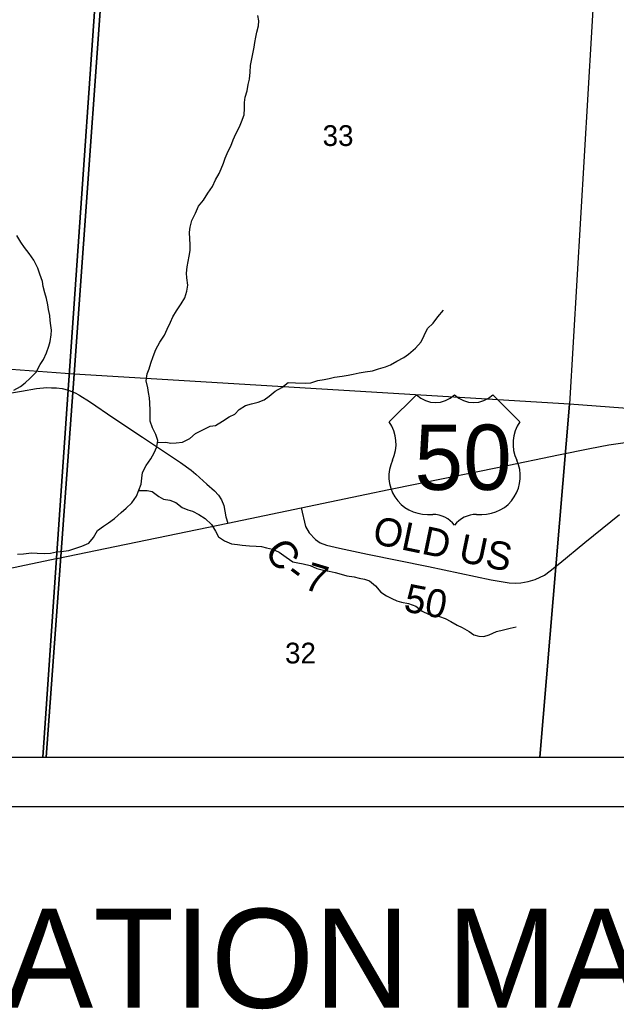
# Model space of a CAD drawing. Extents: x 0 to 34, y 0 to 22.
# Drawn here: x 5.007 to 6.21, y 13.591 to 15.589 of the extents above; entities that cross this region are included whole.
import ezdxf

# ---------------------------------------------------------------- set-up
doc = ezdxf.new("R2010")
doc.units = 0
for name, color, linetype in [('Default', 7, 'Continuous'), ('GM_X_County_Road', 7, 'Continuous'), ('GM_X_County_Road_Text', 7, 'Continuous'), ('GM_X_Minor_River', 7, 'Continuous'), ('GM_X_Section', 7, 'Continuous'), ('GM_X_Section_Text', 7, 'Continuous'), ('GM_X_US_Location', 7, 'Continuous'), ('GM_X_US_Route', 7, 'Continuous'), ('GM_X_US_Shield', 7, 'Continuous'), ('SC_Scratch1', 7, 'Continuous'), ('SH_Data', 7, 'Continuous'), ('SH_Text', 7, 'Continuous')]:
    doc.layers.add(name, color=color, linetype=linetype)

msp = doc.modelspace()

# ---------------------------------------------------------------- linework, layer by layer
at = {"layer": 'Default'}
for points in [[(4.0548, 14.1), (5.0601, 14.1), (5.117, 14.8733), (4.1172, 14.9476)], [(5.0601, 14.1), (6.0561, 14.1), (6.1161, 14.8127), (5.117, 14.8733)], [(6.0561, 14.1), (7.0384, 14.1), (7.0398, 14.1229), (7.0661, 14.5598), (7.0761, 14.7365), (6.6458, 14.7734), (6.1161, 14.8127)]]:
    msp.add_lwpolyline(points, close=True, dxfattribs=at)
at = {"layer": 'GM_X_County_Road'}
msp.add_line((5.4268, 14.5725), (5.5748, 14.6035), dxfattribs=at)
for points in [[(4.9443, 14.8282), (5.0106, 14.8388), (5.041, 14.8443), (5.0614, 14.8464), (5.0708, 14.8461), (5.0812, 14.8457), (5.0925, 14.8441), (5.1051, 14.8409), (5.1069, 14.8404), (5.1187, 14.836), (5.1262, 14.8313)], [(5.1262, 14.8313), (5.1279, 14.8302), (5.1477, 14.818), (5.1969, 14.7847), (5.2544, 14.7462), (5.3013, 14.715), (5.3311, 14.6952), (5.3526, 14.6793), (5.3621, 14.6711), (5.3842, 14.6511), (5.4001, 14.6378), (5.4082, 14.6293), (5.4141, 14.6199), (5.4185, 14.6084), (5.423, 14.5851), (5.4268, 14.5725)], [(5.5748, 14.6035), (5.5834, 14.566), (5.591, 14.5532), (5.6035, 14.5393), (5.6131, 14.5328), (5.6259, 14.5279), (5.6523, 14.5219), (5.7088, 14.5097), (5.8318, 14.4848), (5.9583, 14.4581), (5.9942, 14.4522), (6.0077, 14.4516), (6.0179, 14.4522), (6.0326, 14.4546), (6.0469, 14.4589), (6.0656, 14.4673), (6.0775, 14.4764), (6.0964, 14.4919), (6.147, 14.5332), (6.2168, 14.5903)]]:
    msp.add_lwpolyline(points, dxfattribs=at)
at = {"layer": 'GM_X_Minor_River'}
for points in [[(5.4703, 15.4694), (5.4717, 15.4833), (5.4728, 15.4969), (5.4743, 15.5068), (5.4773, 15.5205), (5.4799, 15.5337), (5.4814, 15.5432), (5.4836, 15.5542), (5.4851, 15.5637), (5.4885, 15.577), (5.4896, 15.5872), (5.4877, 15.5975)], [(5.0024, 14.5096), (5.0145, 14.5108), (5.0308, 14.5126), (5.0421, 14.5122), (5.0572, 14.5111), (5.069, 14.5122), (5.0814, 14.5148), (5.0951, 14.5159), (5.1057, 14.5174), (5.1321, 14.5257), (5.1461, 14.5322), (5.156, 14.5435), (5.1636, 14.5575), (5.1761, 14.5662), (5.1863, 14.5734), (5.198, 14.5821), (5.2117, 14.5938), (5.2215, 14.6025), (5.2333, 14.6135), (5.2427, 14.6271), (5.2473, 14.6389), (5.2519, 14.6514), (5.253, 14.6635), (5.2549, 14.6749), (5.2618, 14.6889), (5.2716, 14.7025), (5.2784, 14.7146), (5.2838, 14.7268), (5.2857, 14.7396), (5.2819, 14.7518), (5.2747, 14.7647), (5.2698, 14.7783), (5.2699, 14.7904), (5.2703, 14.8003), (5.2695, 14.8158), (5.2688, 14.8257), (5.2669, 14.8363), (5.2654, 14.8458), (5.262, 14.8602), (5.264, 14.8738), (5.2678, 14.8844), (5.2715, 14.8954), (5.2761, 14.909), (5.2818, 14.9231), (5.2894, 14.9378), (5.2989, 14.9522), (5.3046, 14.9643), (5.311, 14.9787), (5.316, 14.9889), (5.3235, 15.0011), (5.333, 15.0151), (5.3398, 15.0272), (5.3444, 15.0408), (5.3459, 15.0533), (5.3444, 15.0677), (5.3437, 15.0772), (5.3445, 15.0901), (5.3468, 15.1011), (5.3491, 15.1117), (5.3506, 15.1234), (5.3506, 15.1356), (5.3499, 15.1458), (5.3495, 15.1598), (5.3507, 15.1704), (5.3545, 15.1837), (5.3613, 15.1984), (5.3678, 15.2125), (5.378, 15.2246), (5.3863, 15.239), (5.3958, 15.2522), (5.4019, 15.2655), (5.4095, 15.2783), (5.4133, 15.2882), (5.4178, 15.2995), (5.4216, 15.3098), (5.4277, 15.3234), (5.4326, 15.3336), (5.4379, 15.3469), (5.4433, 15.3586), (5.4501, 15.3726), (5.4546, 15.3832), (5.4596, 15.3973), (5.4607, 15.4098), (5.4608, 15.4223), (5.4619, 15.4325), (5.4661, 15.4454), (5.468, 15.4586), (5.4703, 15.4694)], [(4.995, 14.8413), (5.0082, 14.8484), (5.0181, 14.8556), (5.0279, 14.8651), (5.0404, 14.8776), (5.0484, 14.8931), (5.0552, 14.9029), (5.0609, 14.9162), (5.0659, 14.9298), (5.0682, 14.9393), (5.0704, 14.9526), (5.0712, 14.9624), (5.0697, 14.9719), (5.0682, 14.9817), (5.0679, 14.992), (5.0652, 15.0037), (5.0634, 15.0136), (5.0607, 15.0265), (5.0573, 15.0375), (5.054, 15.0507), (5.0528, 15.0602), (5.0472, 15.075), (5.0434, 15.0871), (5.0351, 15.1034), (5.0257, 15.1171), (5.0166, 15.1292), (5.0091, 15.1402), (5.0012, 15.1531)], [(5.2851, 14.7355), (5.3019, 14.7358), (5.3121, 14.7343), (5.3227, 14.7347), (5.3352, 14.7361), (5.35, 14.7437), (5.3613, 14.7535), (5.3791, 14.7626), (5.3912, 14.7683), (5.4018, 14.7698), (5.4158, 14.7785), (5.4295, 14.7875), (5.4412, 14.7925), (5.4499, 14.8023), (5.4628, 14.8102), (5.4745, 14.8132), (5.4878, 14.8166), (5.4999, 14.8215), (5.5101, 14.8287), (5.5226, 14.8389), (5.5355, 14.8465), (5.5487, 14.8563), (5.5631, 14.8559), (5.5835, 14.8551), (5.5945, 14.8559), (5.6081, 14.8608), (5.621, 14.8623), (5.6315, 14.8646), (5.6421, 14.8676), (5.6576, 14.8691), (5.6694, 14.8713), (5.6796, 14.8732), (5.6917, 14.8758), (5.7042, 14.8781), (5.7189, 14.8803), (5.731, 14.8841), (5.7447, 14.8879), (5.7553, 14.8924), (5.7678, 14.8996), (5.7818, 14.9068), (5.7916, 14.914), (5.8052, 14.9261), (5.8166, 14.9386), (5.8231, 14.9514), (5.8299, 14.9654), (5.8409, 14.9764), (5.8507, 14.9889), (5.8621, 15.0025)], [(5.2471, 14.6384), (5.2643, 14.6385), (5.2741, 14.6362), (5.2874, 14.6263), (5.2972, 14.6206), (5.31, 14.6187), (5.3218, 14.6141), (5.335, 14.6039), (5.3459, 14.5997), (5.3558, 14.597), (5.3686, 14.5902), (5.3811, 14.5822), (5.3936, 14.5701), (5.4019, 14.5564), (5.4079, 14.5447), (5.4203, 14.5367), (5.434, 14.531), (5.4461, 14.5291), (5.4559, 14.5279), (5.4703, 14.5268), (5.4842, 14.526), (5.4945, 14.5256), (5.505, 14.5229), (5.5171, 14.5202), (5.5307, 14.5142), (5.5447, 14.5039), (5.5579, 14.4944), (5.5682, 14.4925), (5.5791, 14.4906), (5.5927, 14.4868), (5.6063, 14.4807), (5.6199, 14.4773), (5.6313, 14.4757), (5.6434, 14.4727), (5.6555, 14.4693), (5.6672, 14.4658), (5.6819, 14.4639), (5.6921, 14.4616), (5.7027, 14.4593), (5.7126, 14.4559), (5.725, 14.4457), (5.7356, 14.4331), (5.7473, 14.4255), (5.7575, 14.4202), (5.7677, 14.4156), (5.7775, 14.4126), (5.7915, 14.4099), (5.8059, 14.405), (5.8187, 14.3947), (5.8316, 14.389), (5.8414, 14.3871), (5.8539, 14.3841), (5.8652, 14.3799), (5.8769, 14.3738), (5.8894, 14.3666), (5.8996, 14.362), (5.9136, 14.3537), (5.9234, 14.3468), (5.9333, 14.3442), (5.9431, 14.3434), (5.9544, 14.3472), (5.9692, 14.3536), (5.9832, 14.3573), (5.9964, 14.3604), (6.0085, 14.3634)]]:
    msp.add_lwpolyline(points, dxfattribs=at)
at = {"layer": 'GM_X_Section'}
for points in [[(5.1915, 15.9177), (5.117, 14.8733), (4.1172, 14.9476), (4.189, 15.9719)], [(5.1915, 15.9177), (6.1792, 15.8658), (6.168, 15.6897), (6.1161, 14.8127), (5.117, 14.8733)]]:
    msp.add_lwpolyline(points, close=True, dxfattribs=at)
at = {"layer": 'GM_X_US_Route'}
msp.add_line((5.4268, 14.5725), (5.5748, 14.6035), dxfattribs=at)
for points in [[(5.5748, 14.6035), (5.7069, 14.6307), (5.752, 14.6403), (5.9774, 14.6861), (6.094, 14.7105), (6.1574, 14.7235), (6.1954, 14.7305), (6.2378, 14.7366), (6.2962, 14.7427), (6.3296, 14.7447), (6.3698, 14.7463), (6.4115, 14.746), (6.4229, 14.746), (6.4667, 14.744), (6.4957, 14.7412), (6.5432, 14.736), (6.6028, 14.7269), (6.6553, 14.7165)], [(3.9957, 14.405), (4.0696, 14.4085), (4.1647, 14.4122), (4.3183, 14.4189), (4.4823, 14.426), (4.5874, 14.4303), (4.6235, 14.4326), (4.6596, 14.4348), (4.6854, 14.4367), (4.7362, 14.4408), (4.7884, 14.447), (4.8756, 14.4606), (4.9333, 14.4703), (5.0807, 14.5008), (5.0816, 14.501), (5.222, 14.53), (5.4268, 14.5725)]]:
    msp.add_lwpolyline(points, dxfattribs=at)
at = {"layer": 'GM_X_US_Shield'}
for p, q in [((5.8075, 14.8318), (5.7525, 14.7769)), ((6.0162, 14.7769), (5.9613, 14.8318)), ((5.8294, 14.5901), (5.8404, 14.5901)), ((5.9283, 14.5901), (5.9393, 14.5901))]:
    msp.add_line(p, q, dxfattribs=at)
for centre, radius, start, end in [((5.8459, 14.871), 0.0549, 225.573, 314.427), ((5.9228, 14.871), 0.0549, 225.573, 314.427), ((5.6895, 14.7328), 0.0769, 334.5471, 35.0009), ((6.0792, 14.7328), 0.0769, 144.9991, 205.4529), ((5.8286, 14.667), 0.0769, 154.8319, 270.6383), ((5.9401, 14.667), 0.0769, 269.3617, 25.1681), ((5.8404, 14.5352), 0.0549, 36.8699, 90), ((5.9283, 14.5352), 0.0549, 90, 143.1301)]:
    msp.add_arc(centre, radius, start, end, dxfattribs=at)
at = {"layer": 'SC_Scratch1'}
for points in [[(2.1, 19.1982), (2.1, 14.1), (5.0535, 14.1), (5.0814, 14.5016), (5.1049, 14.8414), (5.1794, 15.9156), (5.2761, 17.2534), (5.2869, 17.4026), (5.3506, 18.2846), (5.3662, 18.4999), (5.4007, 18.9779), (5.182, 18.9932), (4.7997, 19.0196), (4.7394, 19.0241), (4.3628, 19.0495), (3.3448, 19.1146), (2.3572, 19.1804)], [(5.0535, 14.1), (8.9, 14.1), (8.9, 18.7389), (8.2061, 18.7863), (7.2159, 18.8539), (6.8273, 18.8804), (5.9889, 18.9377), (5.4885, 18.9719), (5.4007, 18.9779), (5.3662, 18.4999), (5.3506, 18.2846), (5.2869, 17.4026), (5.2761, 17.2534), (5.1794, 15.9156), (5.1049, 14.8414), (5.0814, 14.5016)]]:
    msp.add_lwpolyline(points, close=True, dxfattribs=at)
at = {"layer": 'SH_Data'}
for p, q in [((2.1, 14.1), (8.9, 14.1)), ((2, 14), (9, 14))]:
    msp.add_line(p, q, dxfattribs=at)

# ---------------------------------------------------------------- texts
at = {"layer": 'GM_X_County_Road_Text'}
for s, height, rotation, p in [('OLD US', 0.05682, 348.2393, (5.7164, 14.5319)), ('C', 0.0568, 305.3054, (5.4992, 14.5158)), ('7', 0.0568, 343.2986, (5.5777, 14.4402)), ('-', 0.0568, 323.422, (5.5399, 14.4637)), ('50', 0.05682, 348.9577, (5.7797, 14.395))]:
    msp.add_text(s, height=height, rotation=rotation, dxfattribs=at).set_placement(p)
at = {"layer": 'GM_X_Section_Text'}
for s, p in [('33', (5.6181, 15.3342)), ('32', (5.5423, 14.2892))]:
    msp.add_text(s, height=0.04186, rotation=0, dxfattribs=at).set_placement(p)
at = {"layer": 'GM_X_US_Location'}
for s in ['0', '/']:
    msp.add_text(s, height=0.000189, dxfattribs=at).set_placement((5.8843, 14.7044))
msp.add_text('50', height=0.000189, rotation=0, dxfattribs=at).set_placement((5.8452, 14.6652))
at = {"layer": 'GM_X_US_Shield'}
msp.add_text('50', height=0.13184, dxfattribs=at).set_placement((5.8035, 14.6396))
at = {"layer": 'SH_Text'}
msp.add_text('LOCATION MAP', height=0.2, dxfattribs=at).set_placement((4.4269, 13.5938))

doc.saveas('drawing.dxf')
